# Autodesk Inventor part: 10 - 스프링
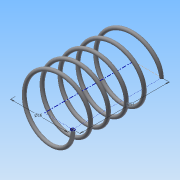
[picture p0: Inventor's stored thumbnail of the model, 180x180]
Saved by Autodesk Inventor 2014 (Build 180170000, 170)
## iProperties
Created: 2015-06
Part Number: 10 - 스프링
Material: 강철, 연강
Document SubType Name: Modeling
Designer: Administrator
Density: 7.86 g/cm^3
Appearance: 강철
Mass: 1.53535 g
Surface Area: 7.89042 cm^2
Volume: 0.195337 cm^3
Author: Administrator
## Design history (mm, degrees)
sketch "스케치1"
  geometry: L1 (0, 0)-(8, 0); L2 (8, 0)-(8, 21.5); L3 (8, 21.5)-(0, 21.5); L4 (0, 21.5)-(0, 0); C1 r 0.5 at (8, 0)
  constraints: 8 end point, 2 parallel, 1 centre point, 1 coincident, 1 horizontal, 1 perpendicular
  dimensions: "d1" = 1 diameter of C1; "d2" = 16 diameter of L2 L4; "d3" = 21.5 distance of L1.end L2.end (derived)
feature "코일1" sketch "스케치1" pitch "d4" = 10; turns "d6" = 5; dims "d5" = 21.5 (= d3), "d7" = 0, angle "d8" = 90 deg, angle "d9" = 90 deg, "d10" = 0, "d11" = 0
sketch "스케치2"
  geometry: L1 (-8.5, 0)-(-7.5, 0) reference; 1 further point
  constraints: 1 horizontal alignment
extrude "돌출1" cut sketch "스케치2" stored distance "d12" = 10; taper "d13" = 0 deg
node "작업 평면1"
sketch "스케치3"
  geometry: L1 (8.5, 0)-(7.5, 0) reference; 1 further point
  constraints: 1 horizontal alignment
extrude "돌출2" cut sketch "스케치3" stored distance "d15" = 10; taper "d16" = 0 deg
node "솔리드1"
node "절단 모서리 투영1"
node "절단 모서리 투영2"
other parameters: "d14" = -21.5 (= -d3)
